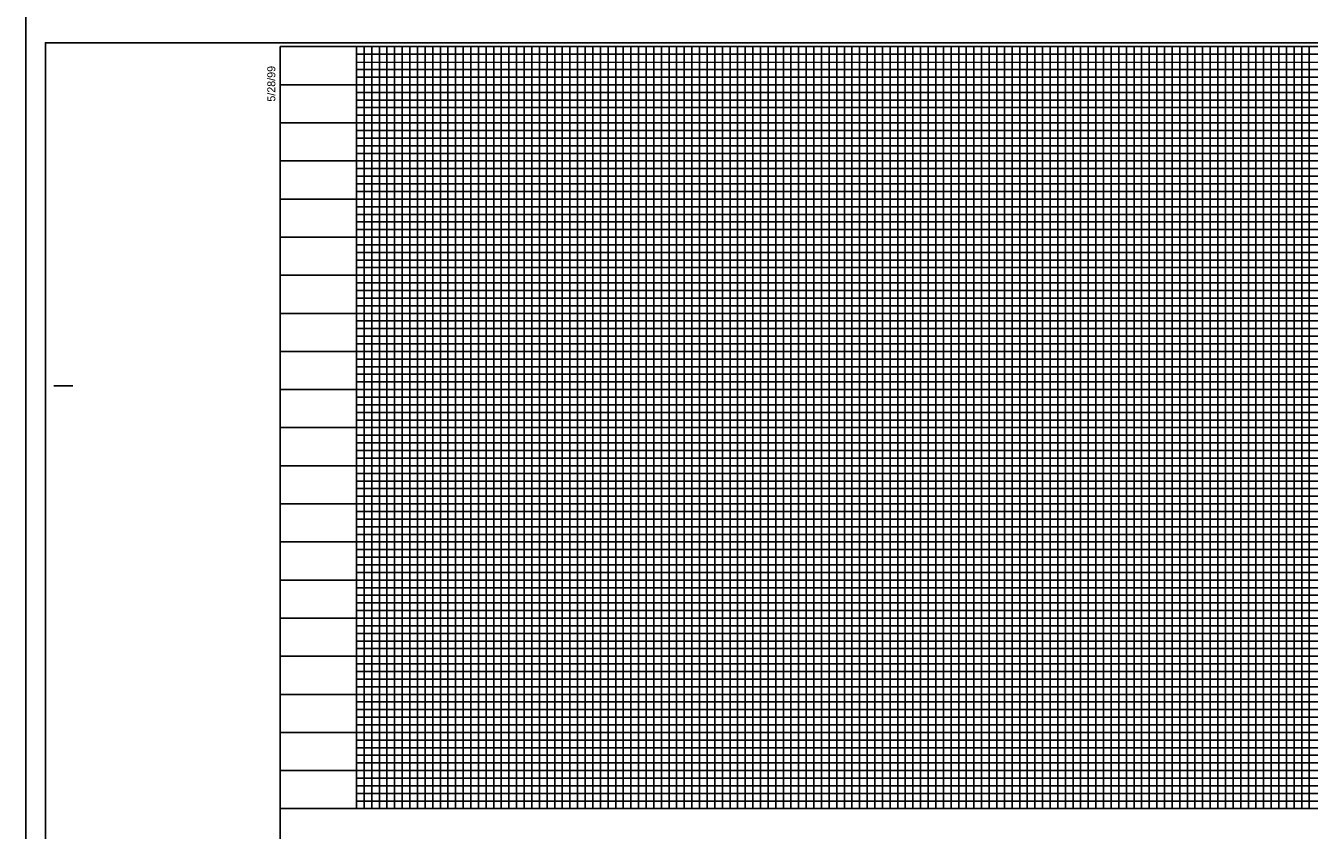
# Model space of a CAD drawing. Extents: x 1755181 to 1757273, y 729911 to 735411.
# Drawn here: x 1755181 to 1756023, y 732672 to 733200 of the extents above; entities that cross this region are included whole.
import ezdxf

# ---------------------------------------------------------------- set-up
doc = ezdxf.new("R2010")
doc.units = 0
for name, color, linetype in [('Scratch_Level_3', 7, 'Continuous'), ('Sheet Cutting Line CELL', 7, 'Continuous'), ('Sheet DOT Grid CELL', 7, 'Continuous'), ('Sheet Plot Border Inside CELL', 7, 'Continuous'), ('Sheet Plot Border Outside CELL', 7, 'Continuous'), ('Sheet Profile CELL', 7, 'Continuous'), ('Sheet Profile Grid Major CELL', 7, 'Continuous'), ('Sheet Profile Grid Middle CELL', 7, 'Continuous'), ('Sheet Profile Grid Minor CELL', 7, 'Continuous')]:
    doc.layers.add(name, color=color, linetype=linetype)

msp = doc.modelspace()

# ---------------------------------------------------------------- linework, layer by layer
at = {"layer": 'Scratch_Level_3'}
msp.add_lwpolyline([(1755347.67, 732660.78), (1755347.67, 733185.78), (1756647.65, 733185.78), (1756647.63, 732952.8), (1756847.67, 732952.8), (1756847.67, 732660.78)], close=True, dxfattribs=at)
at = {"layer": 'Sheet Cutting Line CELL'}
msp.add_line((1755180.67, 733210.78), (1755180.67, 732110.78), dxfattribs=at)
at = {"layer": 'Sheet DOT Grid CELL'}
for p, q in [((1755397.67, 732685.78), (1755397.67, 733185.78)), ((1755447.67, 732685.78), (1755447.67, 733185.78)), ((1755497.67, 732685.78), (1755497.67, 733185.78)), ((1755547.67, 732685.78), (1755547.67, 733185.78)), ((1755597.67, 732685.78), (1755597.67, 733185.78)), ((1755647.67, 732685.78), (1755647.67, 733185.78)), ((1755697.67, 732685.78), (1755697.67, 733185.78)), ((1755747.67, 732685.78), (1755747.67, 733185.78)), ((1755797.67, 732685.78), (1755797.67, 733185.78)), ((1755847.67, 732685.78), (1755847.67, 733185.78)), ((1755897.67, 732685.78), (1755897.67, 733185.78)), ((1755947.67, 732685.78), (1755947.67, 733185.78)), ((1755997.67, 732685.78), (1755997.67, 733185.78)), ((1756647.62, 733135.78), (1755347.67, 733135.78)), ((1756647.62, 733085.78), (1755347.67, 733085.78)), ((1756647.67, 733035.78), (1755347.67, 733035.78)), ((1756647.63, 732985.78), (1755347.67, 732985.78)), ((1756847.67, 732935.78), (1755347.67, 732935.78)), ((1756847.67, 732885.78), (1755347.67, 732885.78)), ((1756847.67, 732835.78), (1755347.67, 732835.78)), ((1756847.67, 732785.78), (1755347.67, 732785.78)), ((1756847.67, 732735.78), (1755347.67, 732735.78))]:
    msp.add_line(p, q, dxfattribs=at)
at = {"layer": 'Sheet Plot Border Inside CELL'}
msp.add_lwpolyline([(1755193.67, 732133.23), (1756860.17, 732133.23), (1756860.17, 733188.33), (1755193.67, 733188.33)], close=True, dxfattribs=at)
at = {"layer": 'Sheet Plot Border Outside CELL'}
msp.add_lwpolyline([(1755180.67, 732110.78), (1756864.67, 732110.78), (1756864.67, 733210.78), (1755180.67, 733210.78)], close=True, dxfattribs=at)
at = {"layer": 'Sheet Profile CELL'}
for p, q in [((1755199.17, 732963.28), (1755211.67, 732963.28)), ((1755347.67, 732685.78), (1756847.67, 732685.78))]:
    msp.add_line(p, q, dxfattribs=at)
msp.add_lwpolyline([(1756847.67, 733185.78), (1755347.67, 733185.78), (1755347.67, 732135.78), (1756847.67, 732135.78)], close=True, dxfattribs=at)
at = {"layer": 'Sheet Profile Grid Major CELL'}
for points in [[(1755397.67, 733185.78), (1755397.67, 732685.78), (1755447.67, 732685.78), (1755447.67, 733185.78), (1755497.67, 733185.78), (1755497.67, 732685.78), (1755547.67, 732685.78), (1755547.67, 733185.78), (1755597.67, 733185.78), (1755597.67, 732685.78), (1755647.67, 732685.78), (1755647.67, 733185.78), (1755697.67, 733185.78), (1755697.67, 732685.78), (1755747.67, 732685.78), (1755747.67, 733185.78), (1755797.67, 733185.78), (1755797.67, 732685.78), (1755847.67, 732685.78), (1755847.67, 733185.78), (1755897.67, 733185.78), (1755897.67, 732685.78), (1755947.67, 732685.78), (1755947.67, 733185.78), (1755997.67, 733185.78), (1755997.67, 732685.78), (1756047.67, 732685.78)], [(1755347.67, 733135.78), (1756647.67, 733135.78)], [(1756647.67, 733085.78), (1755347.67, 733085.78), (1755347.67, 733035.78), (1756647.67, 733035.78)], [(1756647.63, 732985.78), (1755347.67, 732985.78), (1755347.67, 732935.78), (1756847.67, 732935.78)], [(1756847.67, 732885.78), (1755347.67, 732885.78), (1755347.67, 732835.78), (1756847.67, 732835.78)], [(1756847.67, 732785.78), (1755347.67, 732785.78), (1755347.67, 732785.78), (1755347.67, 732735.78), (1756847.67, 732735.78)]]:
    msp.add_lwpolyline(points, dxfattribs=at)
at = {"layer": 'Sheet Profile Grid Middle CELL'}
msp.add_line((1755347.67, 733160.78), (1756647.62, 733160.78), dxfattribs=at)
for points in [[(1755422.67, 733185.78), (1755422.67, 732685.78), (1755472.67, 732685.78), (1755472.67, 733185.78), (1755522.67, 733185.78), (1755522.67, 732685.78), (1755572.67, 732685.78), (1755572.67, 733185.78), (1755622.67, 733185.78), (1755622.67, 732685.78), (1755672.67, 732685.78), (1755672.67, 733185.78), (1755722.67, 733185.78), (1755722.67, 732685.78), (1755772.67, 732685.78), (1755772.67, 733185.78), (1755822.67, 733185.78), (1755822.67, 732685.78), (1755872.67, 732685.78), (1755872.67, 733185.78), (1755922.67, 733185.78), (1755922.67, 732685.78), (1755972.67, 732685.78), (1755972.67, 732685.78), (1755972.67, 733185.78), (1756022.67, 733185.78), (1756022.67, 732685.78), (1756072.67, 732685.78)], [(1756647.67, 733110.78), (1755347.67, 733110.78), (1755347.67, 733060.78), (1756647.67, 733060.78)], [(1756647.62, 733010.78), (1755347.67, 733010.78), (1755347.67, 732960.78), (1756647.63, 732960.78)], [(1756847.67, 732910.78), (1755347.67, 732910.78), (1755347.67, 732860.78), (1756847.67, 732860.78)], [(1756847.67, 732810.78), (1755347.67, 732810.78), (1755347.67, 732760.78), (1756847.67, 732760.78)], [(1756847.67, 732710.78), (1755347.67, 732710.78)]]:
    msp.add_lwpolyline(points, dxfattribs=at)
at = {"layer": 'Sheet Profile Grid Minor CELL'}
for p, q in [((1755397.67, 733180.78), (1756647.67, 733180.78)), ((1755397.67, 733175.78), (1755397.67, 733175.78)), ((1756647.67, 733175.78), (1755397.67, 733175.43)), ((1755397.67, 733170.78), (1756647.67, 733170.78)), ((1756647.62, 733050.78), (1755397.67, 733050.78)), ((1756647.67, 733045.78), (1755397.67, 733045.78)), ((1756647.67, 733040.78), (1755397.67, 733040.78)), ((1755397.67, 733030.78), (1756647.67, 733030.78)), ((1756647.67, 733025.78), (1755397.67, 733025.78)), ((1755397.67, 733020.78), (1756647.62, 733020.78)), ((1756647.62, 733000.78), (1755397.67, 733000.78)), ((1755397.67, 732995.78), (1756647.62, 732995.78)), ((1756647.63, 732975.78), (1755397.67, 732975.78)), ((1755397.67, 732970.78), (1756647.63, 732970.78)), ((1756797.67, 732950.78), (1755397.67, 732950.78)), ((1755397.67, 732945.78), (1756797.67, 732945.78)), ((1756797.67, 732940.78), (1755397.67, 732940.78)), ((1755397.67, 732930.78), (1756797.67, 732930.78)), ((1756797.67, 732925.78), (1755397.67, 732925.78)), ((1755397.67, 732920.78), (1756797.67, 732920.78)), ((1756797.67, 732915.78), (1755397.67, 732915.78)), ((1755397.67, 732905.78), (1756797.67, 732905.78)), ((1756797.67, 732900.78), (1755397.67, 732900.78)), ((1755397.67, 732895.78), (1756797.67, 732895.78)), ((1756797.67, 732890.78), (1755397.67, 732890.78)), ((1755397.67, 732880.78), (1756797.67, 732880.78)), ((1756797.67, 732875.78), (1755397.67, 732875.78)), ((1755397.67, 732870.78), (1756797.67, 732870.78)), ((1756797.67, 732865.78), (1755397.67, 732865.78)), ((1755397.67, 732855.78), (1756797.67, 732855.78)), ((1756797.67, 732850.78), (1755397.67, 732850.78)), ((1755397.67, 732845.78), (1756797.67, 732845.78)), ((1756797.67, 732840.78), (1755397.67, 732840.78)), ((1755397.67, 732830.78), (1756797.67, 732830.78)), ((1756797.67, 732825.78), (1755397.67, 732825.78)), ((1755397.67, 732820.78), (1756797.67, 732820.78)), ((1756797.67, 732815.78), (1755397.67, 732815.78)), ((1755397.67, 732805.78), (1756797.67, 732805.78)), ((1756797.67, 732800.78), (1755397.67, 732800.78)), ((1756797.67, 732795.78), (1755397.67, 732795.78)), ((1756797.67, 732790.78), (1755397.67, 732790.78)), ((1755397.67, 732780.78), (1756797.67, 732780.78)), ((1756797.67, 732775.78), (1755397.67, 732775.78)), ((1755397.67, 732770.78), (1756797.67, 732770.78)), ((1756797.67, 732765.78), (1755397.67, 732765.78)), ((1755397.67, 732755.78), (1756797.67, 732755.78)), ((1756797.67, 732750.78), (1755397.67, 732750.78)), ((1755397.67, 732745.78), (1756797.67, 732745.78)), ((1756797.67, 732740.78), (1755397.67, 732740.78)), ((1755397.67, 732730.78), (1756797.67, 732730.78)), ((1756797.67, 732725.78), (1755397.67, 732725.78)), ((1755397.67, 732720.78), (1756797.67, 732720.78)), ((1756797.67, 732715.78), (1755397.67, 732715.78)), ((1755397.67, 732705.78), (1756797.67, 732705.78)), ((1756797.67, 732700.78), (1755397.67, 732700.78)), ((1755397.67, 732695.78), (1756797.67, 732695.78))]:
    msp.add_line(p, q, dxfattribs=at)
for points in [[(1755402.67, 733185.78), (1755402.67, 732685.78), (1755407.67, 732685.78), (1755407.67, 733185.78), (1755412.67, 733185.78), (1755412.67, 732685.78), (1755417.67, 732685.78), (1755417.67, 733185.78), (1755427.67, 733185.78), (1755427.67, 732685.78), (1755432.67, 732685.78), (1755432.67, 733185.78), (1755437.67, 733185.78), (1755437.67, 732685.78), (1755442.67, 732685.78), (1755452.67, 732685.78), (1755457.67, 732685.78), (1755457.67, 733185.78), (1755462.67, 733185.78), (1755462.67, 732685.78), (1755467.67, 732685.78), (1755467.67, 733185.78), (1755477.67, 733185.78), (1755477.67, 732685.78), (1755482.67, 732685.78), (1755482.67, 733185.78), (1755487.67, 733185.78), (1755487.67, 732685.78), (1755492.67, 732685.78), (1755492.67, 733185.78), (1755502.67, 733185.78), (1755502.67, 732685.78), (1755507.67, 732685.78), (1755507.67, 733185.78), (1755512.67, 733185.78), (1755512.67, 732685.78), (1755517.67, 732685.78), (1755517.67, 733185.78), (1755527.67, 733185.78), (1755527.67, 732685.78), (1755532.67, 732685.78), (1755532.67, 733185.78), (1755537.67, 733185.78), (1755537.67, 732685.78), (1755542.67, 732685.78), (1755542.67, 733185.78), (1755552.67, 733185.78), (1755552.67, 732685.78), (1755557.67, 732685.78), (1755557.67, 733185.78), (1755562.67, 733185.78), (1755562.67, 732685.78), (1755567.67, 732685.78), (1755567.67, 733185.78), (1755577.67, 733185.78), (1755577.67, 732685.78), (1755582.67, 732685.78), (1755582.67, 733185.78), (1755587.67, 733185.78), (1755587.67, 732685.78), (1755592.67, 732685.78), (1755592.67, 733185.78), (1755602.67, 733185.78), (1755602.67, 732685.78), (1755607.67, 732685.78), (1755607.67, 733185.78), (1755612.67, 733185.78), (1755612.67, 732685.78)], [(1755442.67, 732685.78), (1755442.67, 733185.78), (1755452.67, 733185.78), (1755452.67, 732685.78)], [(1755612.67, 732685.78), (1755617.67, 732685.78), (1755617.67, 733185.78), (1755627.67, 733185.78), (1755627.67, 732685.78), (1755632.67, 732685.78), (1755632.67, 733185.78), (1755637.67, 733185.78), (1755637.67, 732685.78), (1755642.67, 732685.78), (1755642.67, 733185.78), (1755652.67, 733185.78), (1755652.67, 732685.78), (1755657.67, 732685.78), (1755657.67, 733185.78), (1755662.67, 733185.78), (1755662.67, 732685.78), (1755667.67, 732685.78), (1755667.67, 733185.78), (1755677.67, 733185.78), (1755677.67, 732685.78), (1755682.67, 732685.78), (1755682.67, 733185.78), (1755687.67, 733185.78), (1755687.67, 732685.78), (1755692.67, 732685.78), (1755692.67, 733185.78), (1755702.67, 733185.78), (1755702.67, 732685.78), (1755707.67, 732685.78), (1755707.67, 733185.78), (1755712.67, 733185.78), (1755712.67, 732685.78), (1755717.67, 732685.78), (1755717.67, 733185.78), (1755727.67, 733185.78), (1755727.67, 732685.78), (1755732.67, 732685.78), (1755732.67, 733185.78), (1755737.67, 733185.78), (1755737.67, 732685.78), (1755742.67, 732685.78), (1755742.67, 733185.78), (1755752.67, 733185.78), (1755752.67, 732685.78), (1755757.67, 732685.78), (1755757.67, 733185.78), (1755762.67, 733185.78), (1755762.67, 732685.78), (1755767.67, 732685.78), (1755767.67, 733185.78), (1755777.67, 733185.78), (1755777.67, 732685.78), (1755782.67, 732685.78), (1755782.67, 733185.78), (1755787.67, 733185.78), (1755787.67, 732685.78), (1755792.67, 732685.78), (1755792.67, 733185.78), (1755802.67, 733185.78), (1755802.67, 732685.78), (1755807.67, 732685.78), (1755807.67, 733185.78), (1755812.67, 733185.78), (1755812.67, 732685.78), (1755817.67, 732685.78), (1755817.67, 733185.78), (1755827.67, 733185.78), (1755827.67, 732685.78), (1755832.67, 732685.78), (1755832.67, 733185.78), (1755837.67, 733185.78), (1755837.67, 732685.78), (1755842.67, 732685.78), (1755842.67, 733185.78), (1755852.67, 733185.78), (1755852.67, 732685.78), (1755857.67, 732685.78), (1755857.67, 733185.78), (1755862.67, 733185.78), (1755862.67, 732685.78), (1755867.67, 732685.78), (1755867.67, 733185.78), (1755877.67, 733185.78), (1755877.67, 732685.78), (1755882.67, 732685.78), (1755882.67, 733185.78), (1755887.67, 733185.78), (1755887.67, 732685.78), (1755892.67, 732685.78), (1755892.67, 733185.78), (1755902.67, 733185.78), (1755902.67, 732685.78), (1755907.67, 732685.78), (1755907.67, 733185.78), (1755912.67, 733185.78), (1755912.67, 732685.78), (1755917.67, 732685.78), (1755917.67, 733185.78), (1755927.67, 733185.78)], [(1755927.67, 733185.78), (1755927.67, 732685.78), (1755932.67, 732685.78), (1755932.67, 733185.78), (1755937.67, 733185.78), (1755937.67, 732685.78), (1755942.67, 732685.78), (1755942.67, 733185.78), (1755952.67, 733185.78), (1755952.67, 732685.78), (1755957.67, 732685.78), (1755957.67, 733185.78), (1755962.67, 733185.78), (1755962.67, 732685.78), (1755967.67, 732685.78), (1755967.67, 733185.78), (1755977.67, 733185.78), (1755977.67, 732685.78), (1755982.67, 732685.78), (1755982.67, 733185.78), (1755987.67, 733185.78), (1755987.67, 732685.78), (1755992.67, 732685.78), (1755992.67, 733185.78), (1756002.67, 733185.78), (1756002.67, 732685.78), (1756007.67, 732685.78), (1756007.67, 733185.78), (1756012.67, 733185.78), (1756012.67, 732685.78), (1756017.67, 732685.78), (1756017.67, 733185.78), (1756027.67, 733185.78)], [(1756647.67, 733165.78), (1755397.67, 733165.78), (1755397.67, 733155.78), (1756647.67, 733155.78)], [(1756647.62, 733150.78), (1755397.67, 733150.78), (1755397.67, 733145.78), (1756647.67, 733145.78)], [(1756647.67, 733140.78), (1755397.67, 733140.78), (1755397.67, 733130.78), (1756647.67, 733130.78)], [(1756647.67, 733125.78), (1755397.67, 733125.78), (1755397.67, 733120.78), (1756647.67, 733120.78)], [(1756647.67, 733115.78), (1755397.67, 733115.78), (1755397.67, 733105.78), (1756647.67, 733105.78)], [(1756647.67, 733100.78), (1755397.67, 733100.78), (1755397.67, 733095.78), (1756647.67, 733095.78)], [(1756647.67, 733090.78), (1755397.67, 733090.78), (1755397.67, 733080.78), (1756647.67, 733080.78)], [(1756647.67, 733075.68), (1755397.77, 733075.68), (1755397.77, 733070.78), (1756647.67, 733070.78)], [(1756647.67, 733065.78), (1755397.67, 733065.78), (1755397.67, 733055.78), (1756647.67, 733055.78)], [(1756647.62, 733015.78), (1755397.67, 733015.78), (1755397.67, 733005.78), (1756647.62, 733005.78)], [(1756647.62, 732990.78), (1755397.67, 732990.78), (1755397.67, 732980.78), (1756647.63, 732980.78)], [(1756647.63, 732965.78), (1755397.67, 732965.78), (1755397.67, 732955.78), (1756647.63, 732955.78)], [(1756797.67, 732690.78), (1755397.67, 732690.78)]]:
    msp.add_lwpolyline(points, dxfattribs=at)

# ---------------------------------------------------------------- texts
at = {"layer": 'Sheet Profile CELL'}
msp.add_text('5/28/99', height=5.25, rotation=90, dxfattribs=at).set_placement((1755344.43, 733149.7))

doc.saveas('drawing.dxf')
